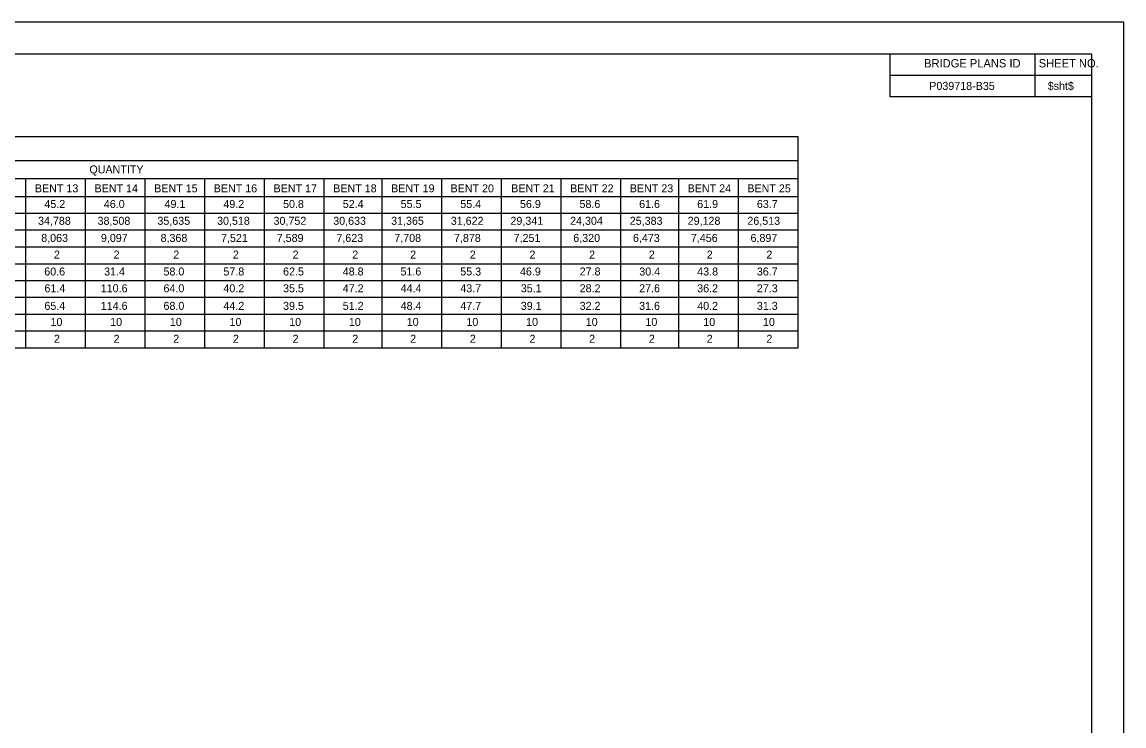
# Model space of a CAD drawing. Extents: x -149.6 to -53.3, y -21.7 to 37.
# Drawn here: x -99.5 to -53.61, y 7.67 to 37.01 of the extents above; entities that cross this region are included whole.
import ezdxf

# ---------------------------------------------------------------- set-up
doc = ezdxf.new("R2010")
doc.units = 0
for name, color, linetype in [('BR_AUTO DIMENSION', 7, 'Continuous'), ('BR_BORDER LINES', 7, 'Continuous'), ('BR_TEXT', 7, 'Continuous'), ('Level 31', 7, 'Continuous')]:
    doc.layers.add(name, color=color, linetype=linetype)

msp = doc.modelspace()

# ---------------------------------------------------------------- linework, layer by layer
at = {"layer": 'BR_AUTO DIMENSION'}
for p, q in [((-140.673, 32.241), (-67.178, 32.241)), ((-67.178, 23.437), (-67.178, 32.241)), ((-140.673, 31.241), (-67.178, 31.241)), ((-124.188, 30.491), (-67.178, 30.491)), ((-99.337, 23.437), (-99.337, 30.491)), ((-96.852, 23.437), (-96.852, 30.491)), ((-94.367, 23.437), (-94.367, 30.491)), ((-91.882, 23.437), (-91.882, 30.491)), ((-89.397, 23.437), (-89.397, 30.491)), ((-86.911, 23.437), (-86.911, 30.491)), ((-84.5, 23.437), (-84.5, 30.491)), ((-82.015, 23.437), (-82.015, 30.491)), ((-79.53, 23.437), (-79.53, 30.491)), ((-77.044, 23.437), (-77.044, 30.491)), ((-74.559, 23.437), (-74.559, 30.491)), ((-72.148, 23.437), (-72.148, 30.491)), ((-69.663, 23.437), (-69.663, 30.491)), ((-140.673, 29.741), (-67.178, 29.741)), ((-140.673, 29.041), (-67.178, 29.041)), ((-140.673, 28.341), (-67.178, 28.341)), ((-140.673, 27.645), (-67.178, 27.645)), ((-140.673, 26.937), (-67.178, 26.937)), ((-140.673, 26.237), (-67.178, 26.237)), ((-140.673, 25.537), (-67.178, 25.537)), ((-140.673, 24.837), (-67.178, 24.837)), ((-140.673, 24.137), (-67.178, 24.137)), ((-140.673, 23.437), (-67.178, 23.437))]:
    msp.add_line(p, q, dxfattribs=at)
at = {"layer": 'BR_BORDER LINES'}
for p, q in [((-54.941, 35.673), (-144.717, 35.673)), ((-63.347, 33.896), (-63.347, 35.673)), ((-57.303, 33.896), (-57.303, 35.673)), ((-54.941, -20.327), (-54.941, 35.673)), ((-63.347, 34.794), (-54.941, 34.794)), ((-57.303, 34.794), (-54.941, 34.794)), ((-54.941, 33.896), (-63.347, 33.896))]:
    msp.add_line(p, q, dxfattribs=at)
at = {"layer": 'Level 31'}
msp.add_lwpolyline([(-149.606, -21.66), (-53.606, -21.66), (-53.606, 37.007), (-149.606, 37.007)], close=True, dxfattribs=at)

# ---------------------------------------------------------------- texts
at = {"layer": 'BR_TEXT'}
for s, height, p in [('BRIDGE PLANS ID', 0.34667, (-61.93, 35.115)), ('SHEET NO.', 0.3467, (-57.155, 35.115)), ('P039718-B35', 0.33333, (-61.714, 34.178)), ('$sht$', 0.3333, (-56.781, 34.178))]:
    msp.add_text(s, height=height, dxfattribs=at).set_placement(p)
for s, height, p in [('QUANTITY', 0.3333, (-96.695, 30.699)), ('BENT 13', 0.3333, (-98.966, 29.91)), ('BENT 14', 0.3333, (-96.481, 29.91)), ('BENT 15', 0.3333, (-93.996, 29.91)), ('BENT 16', 0.3333, (-91.517, 29.91)), ('BENT 17', 0.3333, (-89.025, 29.91)), ('BENT 18', 0.3333, (-86.54, 29.91)), ('BENT 19', 0.3333, (-84.129, 29.91)), ('BENT 20', 0.3333, (-81.654, 29.91)), ('BENT 21', 0.3333, (-79.125, 29.91)), ('BENT 22', 0.3333, (-76.673, 29.91)), ('BENT 23', 0.3333, (-74.188, 29.91)), ('BENT 24', 0.3333, (-71.777, 29.91)), ('BENT 25', 0.3333, (-69.291, 29.91)), ('45.2', 0.3333, (-98.569, 29.257)), ('46.0', 0.3333, (-96.094, 29.257)), ('49.1', 0.3333, (-93.565, 29.257)), ('49.2', 0.3333, (-91.114, 29.257)), ('50.8', 0.3333, (-88.629, 29.257)), ('52.4', 0.3333, (-86.143, 29.257)), ('55.5', 0.3333, (-83.732, 29.257)), ('55.4', 0.3333, (-81.247, 29.257)), ('56.9', 0.3333, (-78.762, 29.257)), ('58.6', 0.3333, (-76.283, 29.257)), ('61.6', 0.3333, (-73.798, 29.257)), ('61.9', 0.3333, (-71.38, 29.257)), ('63.7', 0.3333, (-68.895, 29.257)), ('34,788', 0.3333, (-98.834, 28.557)), ('38,508', 0.3333, (-96.355, 28.557)), ('35,635', 0.3333, (-93.863, 28.557)), ('30,518', 0.3333, (-91.378, 28.557)), ('30,752', 0.3333, (-89.025, 28.557)), ('30,633', 0.3333, (-86.54, 28.557)), ('31,365', 0.3333, (-84.129, 28.557)), ('31,622', 0.3333, (-81.644, 28.557)), ('29,341', 0.3333, (-79.158, 28.557)), ('24,304', 0.3333, (-76.673, 28.557)), ('25,383', 0.3333, (-74.188, 28.557)), ('29,128', 0.3333, (-71.777, 28.557)), ('26,513', 0.3333, (-69.291, 28.557)), ('8,063', 0.3333, (-98.701, 27.843)), ('9,097', 0.3333, (-96.216, 27.843)), ('8,368', 0.3333, (-93.731, 27.843)), ('7,521', 0.3333, (-91.212, 27.843)), ('7,589', 0.3333, (-88.893, 27.843)), ('7,623', 0.3333, (-86.408, 27.843)), ('7,708', 0.3333, (-83.996, 27.843)), ('7,878', 0.3333, (-81.511, 27.843)), ('7,251', 0.3333, (-79.026, 27.843)), ('6,320', 0.3333, (-76.541, 27.843)), ('6,473', 0.3333, (-74.056, 27.843)), ('7,456', 0.3333, (-71.644, 27.843)), ('6,897', 0.3333, (-69.159, 27.843)), ('2', 0.333, (-98.172, 27.15)), ('2', 0.333, (-95.687, 27.15)), ('2', 0.333, (-93.202, 27.15)), ('2', 0.333, (-90.717, 27.15)), ('2', 0.333, (-88.232, 27.15)), ('2', 0.333, (-85.747, 27.15)), ('2', 0.333, (-83.335, 27.15)), ('2', 0.333, (-80.85, 27.15)), ('2', 0.333, (-78.365, 27.15)), ('2', 0.333, (-75.88, 27.15)), ('2', 0.333, (-73.394, 27.15)), ('2', 0.333, (-70.983, 27.15)), ('2', 0.333, (-68.498, 27.15)), ('60.6', 0.3333, (-98.575, 26.445)), ('31.4', 0.3333, (-96.084, 26.445)), ('58.0', 0.3333, (-93.609, 26.445)), ('57.8', 0.3333, (-91.114, 26.445)), ('62.5', 0.3333, (-88.629, 26.445)), ('48.8', 0.3333, (-86.143, 26.445)), ('51.6', 0.3333, (-83.738, 26.445)), ('55.3', 0.3333, (-81.247, 26.445)), ('46.9', 0.3333, (-78.762, 26.445)), ('27.8', 0.3333, (-76.276, 26.445)), ('30.4', 0.3333, (-73.791, 26.445)), ('43.8', 0.3333, (-71.38, 26.445)), ('36.7', 0.3333, (-68.895, 26.445)), ('61.4', 0.3333, (-98.569, 25.745)), ('110.6', 0.3333, (-96.222, 25.745)), ('64.0', 0.3333, (-93.609, 25.745)), ('40.2', 0.3333, (-91.114, 25.745)), ('35.5', 0.3333, (-88.629, 25.745)), ('47.2', 0.3333, (-86.143, 25.745)), ('44.4', 0.3333, (-83.732, 25.745)), ('43.7', 0.3333, (-81.247, 25.745)), ('35.1', 0.3333, (-78.728, 25.745)), ('28.2', 0.3333, (-76.276, 25.745)), ('27.6', 0.3333, (-73.798, 25.745)), ('36.2', 0.3333, (-71.38, 25.745)), ('27.3', 0.3333, (-68.895, 25.745)), ('65.4', 0.3333, (-98.569, 25.013)), ('114.6', 0.3333, (-96.222, 25.013)), ('68.0', 0.3333, (-93.609, 25.013)), ('44.2', 0.3333, (-91.114, 25.013)), ('39.5', 0.3333, (-88.629, 25.013)), ('51.2', 0.3333, (-86.143, 25.013)), ('48.4', 0.3333, (-83.732, 25.013)), ('47.7', 0.3333, (-81.247, 25.013)), ('39.1', 0.3333, (-78.728, 25.013)), ('32.2', 0.3333, (-76.276, 25.013)), ('31.6', 0.3333, (-73.798, 25.013)), ('40.2', 0.3333, (-71.38, 25.013)), ('31.3', 0.3333, (-68.895, 25.013)), ('10', 0.3333, (-98.315, 24.342)), ('10', 0.3333, (-95.83, 24.342)), ('10', 0.3333, (-93.345, 24.342)), ('10', 0.3333, (-90.86, 24.342)), ('10', 0.3333, (-88.374, 24.342)), ('10', 0.3333, (-85.889, 24.342)), ('10', 0.3333, (-83.478, 24.342)), ('10', 0.3333, (-80.993, 24.342)), ('10', 0.3333, (-78.507, 24.342)), ('10', 0.3333, (-76.022, 24.342)), ('10', 0.3333, (-73.537, 24.342)), ('10', 0.3333, (-71.126, 24.342)), ('10', 0.3333, (-68.641, 24.342)), ('2', 0.333, (-98.172, 23.642)), ('2', 0.333, (-95.687, 23.642)), ('2', 0.333, (-93.202, 23.642)), ('2', 0.333, (-90.717, 23.642)), ('2', 0.333, (-88.232, 23.642)), ('2', 0.333, (-85.747, 23.642)), ('2', 0.333, (-83.335, 23.642)), ('2', 0.333, (-80.85, 23.642)), ('2', 0.333, (-78.365, 23.642)), ('2', 0.333, (-75.88, 23.642)), ('2', 0.333, (-73.394, 23.642)), ('2', 0.333, (-70.983, 23.642)), ('2', 0.333, (-68.498, 23.642))]:
    msp.add_text(s, height=height, rotation=0, dxfattribs=at).set_placement(p)

doc.saveas('drawing.dxf')
